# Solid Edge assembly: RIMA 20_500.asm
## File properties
Title: Zylinder
Author: ahadarics
Template: iso metric assembly.asm
Last saved by: ahadarics
Revision: 23
Application: Solid Edge
Username: ahadarics
Dokumentum tartalom típus: 1
Document Number: RIMA 20/500
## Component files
Profilrohr.par
Kolbenstange.par
Kit_1.par
Kit_2.par
Mutter_1.par
Mutter_2.par
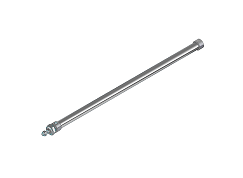
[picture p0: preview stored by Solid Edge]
